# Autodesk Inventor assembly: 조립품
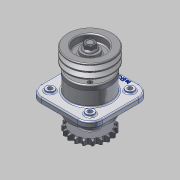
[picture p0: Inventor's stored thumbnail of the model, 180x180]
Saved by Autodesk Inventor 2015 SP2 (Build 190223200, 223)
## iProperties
Created: 2015-07
Part Number: 조립품
Document SubType Name: Assembly
Designer: AMC
Author: AMC
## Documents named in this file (12)
- C:\Users\AMC\Desktop\450735V1010\조립품.iam
- C:\Users\AMC\Desktop\450735V1010\본체.ipt
- C:\Users\AMC\Desktop\450735V1010\2-커버.ipt
- C:\Users\AMC\Desktop\450735V1010\3-축.ipt
- C:\Users\AMC\Desktop\450735V1010\4-V벨트풀리.ipt
- C:\Users\AMC\Desktop\450735V1010\5-체인 스프로킷.ipt
- C:\Users\AMC\Desktop\450735V1010\6-베어링 6206.ipt
- C:\Users\AMC\Desktop\450735V1010\7-부시.ipt
- C:\Users\AMC\Desktop\450735V1010\8-오일실 30x42.ipt
- C:\Users\AMC\Desktop\450735V1010\9-M16-너트.ipt
- C:\Users\AMC\Desktop\450735V1010\10-M6.ipt
- C:\Users\AMC\Desktop\450735V1010\11-키 6x6.ipt
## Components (22 placed, 10 different names)
1. 2-커버:1
2. 3-축:1
3. 4-V벨트풀리:1 — 각도:1
4. 5-체인 스프로킷:1 — 각도:2
5. 6-베어링 6206:1
6. 7-부시:1
7. 8-8-오일실 30x42:1
8. 9-M16 너트:1
9. 11-키 6x6:1 — 각도:1
10. 6-베어링 6206:2
11. 2-커버:2
12. 8-8-오일실 30x42:2
13. 11-키 6x6:2 — 각도:2
14. 9-M16 너트:2
15. 10-M6:1
16. 10-M6:2
17. 10-M6:3
18. 10-M6:4
19. 10-M6:5
20. 10-M6:6
21. 10-M6:7
22. 10-M6:8
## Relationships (2: Angle 2)
- 각도:1 [Angle]: 4-V벨트풀리:1 ↔ 11-키 6x6:1
- 각도:2 [Angle]: 5-체인 스프로킷:1 ↔ 11-키 6x6:2
